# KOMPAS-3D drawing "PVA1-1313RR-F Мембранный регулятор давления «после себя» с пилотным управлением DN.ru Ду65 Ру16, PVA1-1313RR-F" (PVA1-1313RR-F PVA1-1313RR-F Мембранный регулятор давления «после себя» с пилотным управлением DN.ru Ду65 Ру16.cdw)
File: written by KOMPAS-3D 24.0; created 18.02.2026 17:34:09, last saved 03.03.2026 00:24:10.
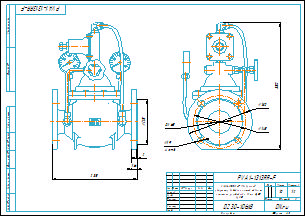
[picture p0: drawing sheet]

Document properties: art: D230-10618; Автор: R2D2; Форматы листов документа: A3; Полное имя файла: PVA1-1313RR-F Мембранный регулятор давления «после себя» с пилотным управлением DN.ru Ду65 Ру16.m3d; Масса: 10; Наименование: PVA1-1313RR-F Мембранный регулятор давления «после себя» с пилотным управлением DN.ru Ду65 Ру16; Количество листов документа: 1; Примечание: D230-10618

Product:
- Part/product: PVA1-1313RR-F Мембранный регулятор давления «после себя» с пилотным управлением DN.ru Ду65 Ру16  | designation PVA1-1313RR-F
    Масса: 10
    Раздел спецификации: Прочие изделия
    Форматы листов документа: A3
    Примечание: D230-10618
    additional columns: D230-10618

Referenced files in E:\Работа\Зайцев\Для компаса\: чертеж DN.ru А3.cdt
Referenced files in E:\Работа\Зайцев\PVA1-1313RR-F Мембранный регулятор давления «после себя» с пилотным управлением DN.ru Ду50-200 Ру16\DN65\: PVA1-1313RR-F Мембранный регулятор давления «после себя» с пилотным управлением DN.ru Ду65 Ру16.m3d
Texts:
  чертеж DN.ru А3.cdt
  PVA1-1313RR-F Мембранный
  регулятор давления «после себя» с
  пилотным управлением DN.ru Ду65
  Ру16
  PVA1-1313RR-F
  prop
  PVA1-1313RR-F Мембранный регулятор давления «после себя» с пилотным управлением DN.ru Ду65 Ру16
  PVA1-1313RR-F PVA1-1313RR-F Мембранный регулятор давления «после себя» с пилотным управлением DN.ru Ду65 Ру16
Dimensions and other numbers on the sheet: 1:2; 0; 1; 2; 10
